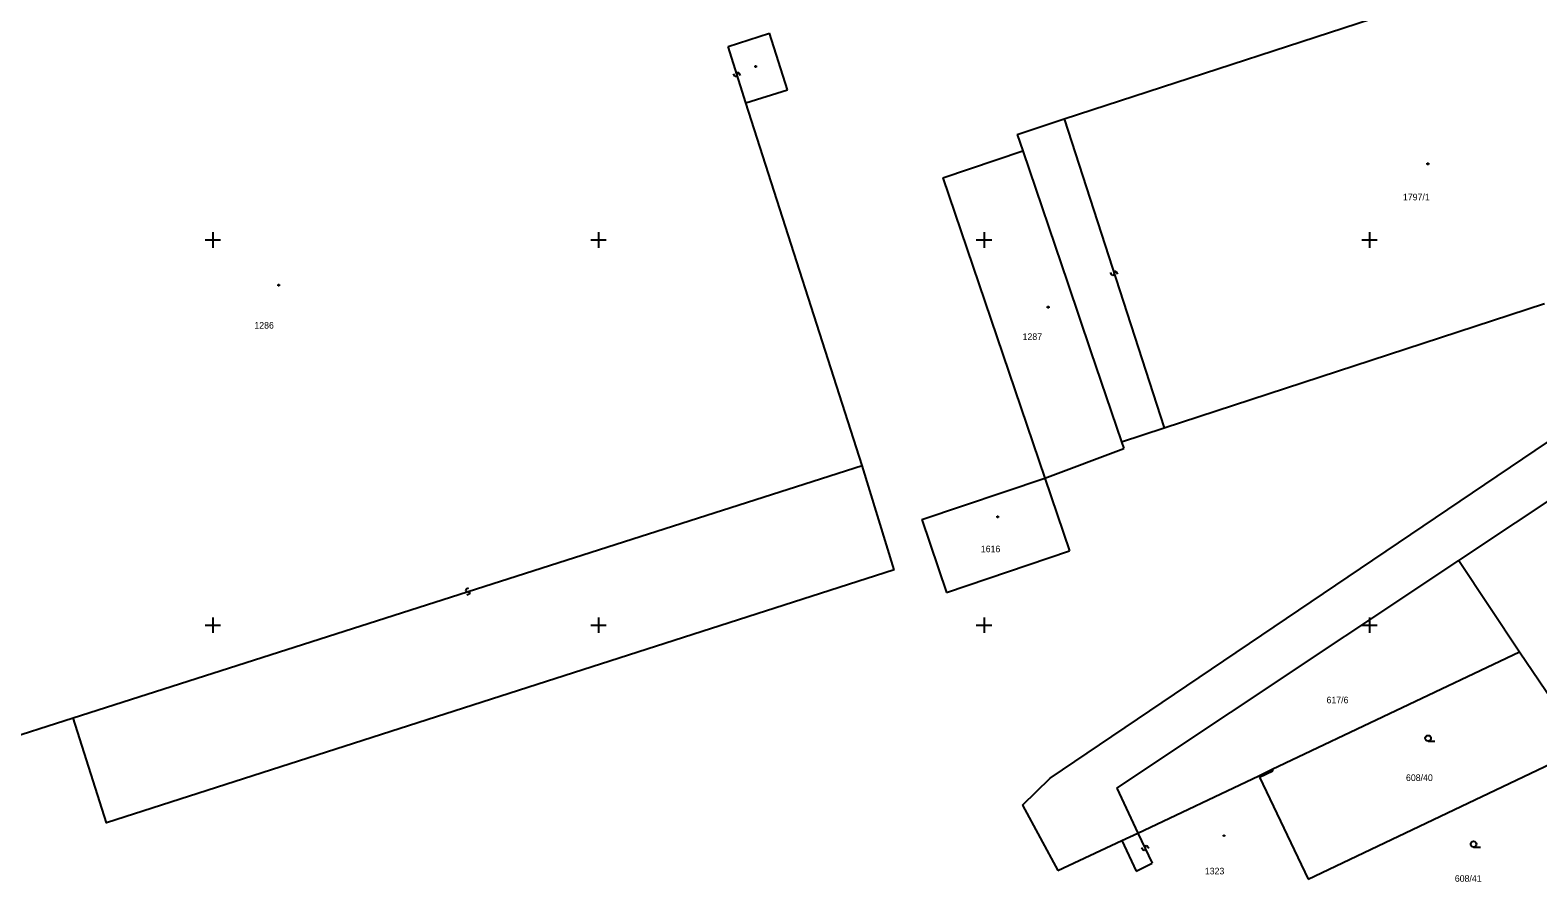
# Model space of a CAD drawing. Extents: x -493352 to -492964, y -1127001 to -1126712.
# Drawn here: x -493214.2 to -493096.9, y -1127000 to -1126933.7 of the extents above; entities that cross this region are included whole.
import ezdxf

# ---------------------------------------------------------------- set-up
doc = ezdxf.new("R2010")
doc.units = 0
doc.layers.add('katastrální mapa', color=7, linetype='Continuous')
doc.layers.add('síť', color=7, linetype='Continuous')

msp = doc.modelspace()

# ---------------------------------------------------------------- linework, layer by layer
at = {"layer": 'katastrální mapa'}
for p, q in [((-493133.77, -1126940.57), (-493104.21, -1126930.93)), ((-493159.91, -1126934.93), (-493156.68, -1126933.9)), ((-493155.3, -1126938.3), (-493156.68, -1126933.9)), ((-493158.53, -1126939.31), (-493159.91, -1126934.93)), ((-493159.4, -1126937.24), (-493159.49, -1126937.05)), ((-493159.33, -1126937.28), (-493159.4, -1126937.24)), ((-493159.27, -1126937.26), (-493159.33, -1126937.28)), ((-493159.23, -1126937.19), (-493159.27, -1126937.26)), ((-493159.21, -1126937.05), (-493159.23, -1126937.19)), ((-493159.17, -1126936.98), (-493159.21, -1126937.05)), ((-493159.11, -1126936.96), (-493159.17, -1126936.98)), ((-493159.04, -1126937), (-493159.11, -1126936.96)), ((-493158.95, -1126937.19), (-493159.04, -1126937)), ((-493157.81, -1126936.45), (-493157.72, -1126936.45)), ((-493157.81, -1126936.54), (-493157.81, -1126936.45)), ((-493157.72, -1126936.54), (-493157.81, -1126936.54)), ((-493157.72, -1126936.45), (-493157.72, -1126936.54)), ((-493158.53, -1126939.31), (-493155.3, -1126938.3)), ((-493149.48, -1126967.56), (-493158.53, -1126939.31)), ((-493137.42, -1126941.78), (-493133.77, -1126940.57)), ((-493133.77, -1126940.57), (-493125.98, -1126964.63)), ((-493137.42, -1126941.78), (-493136.98, -1126943.05)), ((-493143.2, -1126945.15), (-493136.98, -1126943.05)), ((-493136.98, -1126943.05), (-493133.48, -1126953.39)), ((-493105.52, -1126944.03), (-493105.43, -1126944.03)), ((-493105.52, -1126944.12), (-493105.52, -1126944.03)), ((-493105.43, -1126944.12), (-493105.52, -1126944.12)), ((-493105.43, -1126944.03), (-493105.43, -1126944.12)), ((-493143.2, -1126945.15), (-493135.28, -1126968.54)), ((-493130.06, -1126952.72), (-493130.15, -1126952.53)), ((-493129.98, -1126952.76), (-493130.06, -1126952.72)), ((-493129.92, -1126952.74), (-493129.98, -1126952.76)), ((-493129.89, -1126952.67), (-493129.92, -1126952.74)), ((-493129.86, -1126952.53), (-493129.89, -1126952.67)), ((-493129.83, -1126952.46), (-493129.86, -1126952.53)), ((-493129.77, -1126952.44), (-493129.83, -1126952.46)), ((-493129.69, -1126952.48), (-493129.77, -1126952.44)), ((-493129.6, -1126952.67), (-493129.69, -1126952.48)), ((-493194.92, -1126953.47), (-493194.83, -1126953.47)), ((-493194.92, -1126953.56), (-493194.92, -1126953.47)), ((-493194.83, -1126953.56), (-493194.92, -1126953.56)), ((-493194.83, -1126953.47), (-493194.83, -1126953.56)), ((-493133.48, -1126953.39), (-493131.71, -1126958.62)), ((-493135.06, -1126955.18), (-493134.97, -1126955.18)), ((-493135.06, -1126955.27), (-493135.06, -1126955.18)), ((-493134.97, -1126955.18), (-493134.97, -1126955.27)), ((-493125.98, -1126964.63), (-493096.4, -1126954.95)), ((-493134.97, -1126955.27), (-493135.06, -1126955.27)), ((-493131.71, -1126958.62), (-493129.3, -1126965.72)), ((-493103.07, -1126974.96), (-493080.81, -1126960.14)), ((-493134.85, -1126991.91), (-493093.48, -1126963.92)), ((-493129.3, -1126965.72), (-493125.98, -1126964.63)), ((-493129.3, -1126965.72), (-493129.12, -1126966.24)), ((-493135.28, -1126968.54), (-493129.12, -1126966.24)), ((-493210.88, -1126987.21), (-493149.48, -1126967.56)), ((-493147, -1126975.68), (-493149.48, -1126967.56)), ((-493144.83, -1126971.77), (-493135.28, -1126968.54)), ((-493135.28, -1126968.54), (-493133.36, -1126974.2)), ((-493138.98, -1126971.51), (-493138.89, -1126971.51)), ((-493138.98, -1126971.6), (-493138.98, -1126971.51)), ((-493138.89, -1126971.6), (-493138.98, -1126971.6)), ((-493138.89, -1126971.51), (-493138.89, -1126971.6)), ((-493144.83, -1126971.77), (-493142.91, -1126977.44)), ((-493142.91, -1126977.44), (-493133.36, -1126974.2)), ((-493129.67, -1126992.68), (-493103.07, -1126974.96)), ((-493103.07, -1126974.96), (-493098.33, -1126982.06)), ((-493180.3, -1126977.2), (-493180.34, -1126977.28)), ((-493180.34, -1126977.28), (-493180.32, -1126977.34)), ((-493180.32, -1126977.34), (-493180.25, -1126977.37)), ((-493180.11, -1126977.11), (-493180.3, -1126977.2)), ((-493180.25, -1126977.37), (-493180.11, -1126977.4)), ((-493180.11, -1126977.4), (-493180.04, -1126977.43)), ((-493180.04, -1126977.43), (-493180.02, -1126977.49)), ((-493180.06, -1126977.57), (-493180.25, -1126977.66)), ((-493180.02, -1126977.49), (-493180.06, -1126977.57)), ((-493117.59, -1126991.2), (-493098.33, -1126982.06)), ((-493098.33, -1126982.06), (-493093.31, -1126989.53)), ((-493224.17, -1126991.46), (-493210.88, -1126987.21)), ((-493105.45, -1126989.03), (-493104.92, -1126989.03)), ((-493114.79, -1126999.77), (-493093.31, -1126989.53)), ((-493118.62, -1126991.71), (-493117.59, -1126991.2)), ((-493118.57, -1126991.82), (-493117.52, -1126991.32)), ((-493117.59, -1126991.2), (-493117.52, -1126991.32)), ((-493137, -1126994.01), (-493134.85, -1126991.91)), ((-493129.67, -1126992.68), (-493128.03, -1126996.18)), ((-493128.03, -1126996.18), (-493118.62, -1126991.71)), ((-493118.57, -1126991.82), (-493114.79, -1126999.77)), ((-493137, -1126994.01), (-493134.25, -1126999.1)), ((-493129.29, -1126996.75), (-493128.03, -1126996.18)), ((-493128.03, -1126996.18), (-493126.91, -1126998.53)), ((-493134.25, -1126999.1), (-493129.29, -1126996.75)), ((-493129.29, -1126996.75), (-493128.17, -1126999.14)), ((-493127.63, -1126997.5), (-493127.75, -1126997.32)), ((-493127.44, -1126997.21), (-493127.47, -1126997.29)), ((-493127.47, -1126997.29), (-493127.47, -1126997.42)), ((-493127.39, -1126997.18), (-493127.44, -1126997.21)), ((-493127.31, -1126997.21), (-493127.39, -1126997.18)), ((-493127.19, -1126997.39), (-493127.31, -1126997.21)), ((-493121.38, -1126996.34), (-493121.29, -1126996.34)), ((-493121.38, -1126996.43), (-493121.38, -1126996.34)), ((-493121.29, -1126996.43), (-493121.38, -1126996.43)), ((-493121.29, -1126996.34), (-493121.29, -1126996.43)), ((-493101.91, -1126997.27), (-493101.38, -1126997.27)), ((-493128.17, -1126999.14), (-493126.91, -1126998.53)), ((-493127.55, -1126997.53), (-493127.63, -1126997.5)), ((-493127.5, -1126997.5), (-493127.55, -1126997.53)), ((-493127.47, -1126997.42), (-493127.5, -1126997.5))]:
    msp.add_line(p, q, dxfattribs=at)
msp.add_lwpolyline([(-493147, -1126975.68), (-493208.28, -1126995.37), (-493210.88, -1126987.21)], dxfattribs=at)
for centre in [(-493105.45, -1126988.8), (-493101.91, -1126997.04)]:
    msp.add_circle(centre, 0.225, dxfattribs=at)
at = {"layer": 'síť'}
for p, q in [((-493200.6, -1126950), (-493199.4, -1126950)), ((-493200, -1126949.4), (-493200, -1126950.6)), ((-493170.6, -1126950), (-493169.4, -1126950)), ((-493170, -1126949.4), (-493170, -1126950.6)), ((-493140.6, -1126950), (-493139.4, -1126950)), ((-493140, -1126949.4), (-493140, -1126950.6)), ((-493110.6, -1126950), (-493109.4, -1126950)), ((-493110, -1126949.4), (-493110, -1126950.6)), ((-493200, -1126979.4), (-493200, -1126980.6)), ((-493170, -1126979.4), (-493170, -1126980.6)), ((-493140, -1126979.4), (-493140, -1126980.6)), ((-493110, -1126979.4), (-493110, -1126980.6)), ((-493200.6, -1126980), (-493199.4, -1126980)), ((-493170.6, -1126980), (-493169.4, -1126980)), ((-493140.6, -1126980), (-493139.4, -1126980)), ((-493110.6, -1126980), (-493109.4, -1126980))]:
    msp.add_line(p, q, dxfattribs=at)

# ---------------------------------------------------------------- texts
at = {"layer": 'katastrální mapa'}
for s, p in [('1797/1', (-493107.41, -1126946.91)), ('1286', (-493196.77, -1126956.9)), ('1287', (-493137, -1126957.78)), ('1616', (-493140.25, -1126974.31)), ('617/6', (-493113.35, -1126986.07)), ('608/40', (-493107.17, -1126992.12)), ('1323', (-493122.82, -1126999.39)), ('608/41', (-493103.37, -1126999.97))]:
    msp.add_text(s, height=0.51, dxfattribs=at).set_placement(p)

doc.saveas('drawing.dxf')
